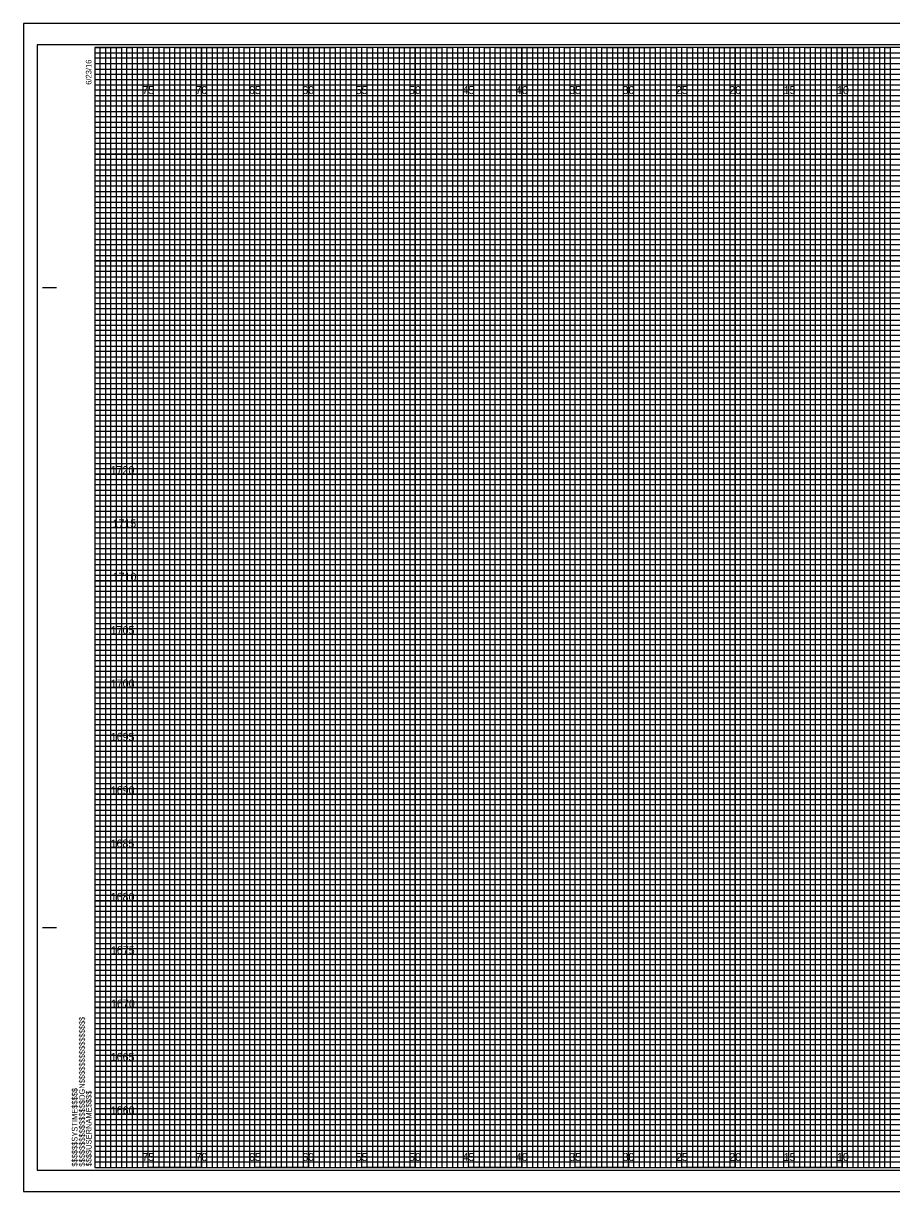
# Model space of a CAD drawing. Extents: x -407 to -239, y -3 to 766.
# Drawn here: x -407 to -325.7, y 436.6 to 546.1 of the extents above; entities that cross this region are included whole.
import ezdxf

# ---------------------------------------------------------------- set-up
doc = ezdxf.new("R2010")
doc.units = 0
for name, color, linetype in [('Raster_Level_0', 7, 'Continuous'), ('Scratch_Level_3', 7, 'Continuous'), ('Sheet Cross Section CELL', 7, 'Continuous'), ('Sheet Cross Section Grid Major CELL', 7, 'Continuous'), ('Sheet Cross Section Grid Middle CELL', 7, 'Continuous'), ('Sheet Cross Section Grid Minor 1 CELL', 7, 'Continuous'), ('Sheet Cross Section Grid Minor 2 CELL', 7, 'Continuous'), ('Sheet Cutting Line CELL', 7, 'Continuous'), ('Sheet DOT Grid CELL', 7, 'Continuous'), ('Sheet Plot Border Inside CELL', 7, 'Continuous'), ('Sheet Plot Border Outside CELL', 7, 'Continuous')]:
    doc.layers.add(name, color=color, linetype=linetype)

msp = doc.modelspace()

# ---------------------------------------------------------------- linework, layer by layer
at = {"layer": 'Sheet Cross Section CELL'}
for p, q in [((-405.22, 521.38), (-403.97, 521.38)), ((-405.17, 521.38), (-403.92, 521.38)), ((-405.22, 461.38), (-403.97, 461.38)), ((-405.17, 461.38), (-403.92, 461.38)), ((-400.32, 438.88), (-400.32, 438.88)), ((-400.32, 438.88), (-400.32, 438.88)), ((-400.32, 438.88), (-400.32, 438.88)), ((-400.32, 438.88), (-400.32, 438.88)), ((-400.32, 438.88), (-400.32, 438.88)), ((-400.32, 438.88), (-400.32, 438.88)), ((-400.32, 438.88), (-400.32, 438.88))]:
    msp.add_line(p, q, dxfattribs=at)
msp.add_lwpolyline([(-240.32, 543.88), (-400.32, 543.88), (-400.32, 438.88), (-240.32, 438.88)], close=True, dxfattribs=at)
at = {"layer": 'Sheet Cross Section Grid Major CELL'}
for p, q in [((-395.32, 543.88), (-400.32, 543.88)), ((-395.32, 438.88), (-395.32, 543.88)), ((-385.32, 543.88), (-390.32, 543.88)), ((-390.32, 543.88), (-390.32, 438.88)), ((-385.32, 438.88), (-385.32, 543.88)), ((-375.32, 543.88), (-380.32, 543.88)), ((-380.32, 543.88), (-380.32, 438.88)), ((-375.32, 438.88), (-375.32, 543.88)), ((-365.32, 543.88), (-370.32, 543.88)), ((-370.32, 543.88), (-370.32, 438.88)), ((-365.32, 438.88), (-365.32, 543.88)), ((-355.32, 543.88), (-360.32, 543.88)), ((-360.32, 543.88), (-360.32, 438.88)), ((-355.32, 438.88), (-355.32, 543.88)), ((-345.32, 543.88), (-350.32, 543.88)), ((-350.32, 543.88), (-350.32, 438.88)), ((-345.32, 438.88), (-345.32, 543.88)), ((-335.32, 543.88), (-340.32, 543.88)), ((-340.32, 543.88), (-340.32, 438.88)), ((-335.32, 438.88), (-335.32, 543.88)), ((-325.32, 543.88), (-330.32, 543.88)), ((-330.32, 543.88), (-330.32, 438.88)), ((-390.32, 438.88), (-395.32, 438.88)), ((-380.32, 438.88), (-385.32, 438.88)), ((-370.32, 438.88), (-375.32, 438.88)), ((-360.32, 438.88), (-365.32, 438.88)), ((-350.32, 438.88), (-355.32, 438.88)), ((-340.32, 438.88), (-345.32, 438.88)), ((-330.32, 438.88), (-335.32, 438.88))]:
    msp.add_line(p, q, dxfattribs=at)
for points in [[(-400.32, 538.88), (-240.32, 538.88), (-240.32, 533.88), (-400.32, 533.88)], [(-400.32, 528.88), (-240.32, 528.88), (-240.32, 523.88), (-400.32, 523.88)], [(-400.32, 518.88), (-240.32, 518.88), (-240.32, 513.88), (-400.32, 513.88)], [(-400.32, 508.88), (-240.32, 508.88), (-240.32, 503.88), (-400.32, 503.88)], [(-400.32, 498.88), (-240.32, 498.88), (-240.32, 493.88), (-400.32, 493.88)], [(-400.32, 488.88), (-240.32, 488.88), (-240.32, 483.88), (-400.32, 483.88)], [(-400.32, 478.88), (-240.32, 478.88), (-240.32, 473.88), (-400.32, 473.88)], [(-400.32, 468.88), (-240.32, 468.88), (-240.32, 463.88), (-400.32, 463.88)], [(-400.32, 458.88), (-240.32, 458.88), (-240.32, 453.88), (-400.32, 453.88)], [(-400.32, 448.88), (-240.32, 448.88), (-240.32, 443.88), (-400.32, 443.88)]]:
    msp.add_lwpolyline(points, dxfattribs=at)
at = {"layer": 'Sheet Cross Section Grid Middle CELL'}
for points in [[(-400.32, 543.88), (-397.82, 543.88), (-397.82, 438.88), (-392.82, 438.88), (-392.82, 543.88), (-387.82, 543.88), (-387.82, 438.88), (-382.82, 438.88), (-382.82, 543.88), (-377.82, 543.88), (-377.82, 438.88), (-372.82, 438.88), (-372.82, 543.88), (-367.82, 543.88), (-367.82, 438.88), (-362.82, 438.88), (-362.82, 543.88), (-357.82, 543.88), (-357.82, 438.88), (-352.82, 438.88), (-352.82, 543.88), (-347.82, 543.88), (-347.82, 438.88), (-342.82, 438.88), (-342.82, 543.88), (-337.82, 543.88), (-337.82, 438.88), (-332.82, 438.88), (-332.82, 543.88), (-327.82, 543.88), (-327.82, 438.88), (-322.82, 438.88)], [(-400.32, 541.38), (-262.82, 541.38)], [(-400.32, 531.38), (-240.32, 531.38), (-240.32, 536.38), (-400.32, 536.38)], [(-400.32, 521.38), (-240.32, 521.38), (-240.32, 526.38), (-400.32, 526.38)], [(-400.32, 511.38), (-240.32, 511.38), (-240.32, 516.38), (-400.32, 516.38)], [(-400.32, 501.38), (-240.32, 501.38), (-240.32, 506.38), (-400.32, 506.38)], [(-400.32, 491.38), (-240.32, 491.38), (-240.32, 496.38), (-400.32, 496.38)], [(-400.32, 481.38), (-240.32, 481.38), (-240.32, 486.38), (-400.32, 486.38)], [(-400.32, 471.38), (-240.32, 471.38), (-240.32, 476.38), (-400.32, 476.38)], [(-400.32, 461.38), (-240.32, 461.38), (-240.32, 466.38), (-400.32, 466.38)], [(-400.32, 451.38), (-240.32, 451.38), (-240.32, 456.38), (-400.32, 456.38)], [(-400.32, 441.38), (-240.32, 441.38), (-240.32, 446.38), (-400.32, 446.38)]]:
    msp.add_lwpolyline(points, dxfattribs=at)
at = {"layer": 'Sheet Cross Section Grid Minor 1 CELL'}
for p, q in [((-400.32, 543.38), (-270.32, 543.38)), ((-270.32, 542.87), (-400.32, 542.87)), ((-400.32, 542.87), (-400.32, 542.38)), ((-400.32, 542.38), (-270.32, 542.38)), ((-270.32, 541.82), (-400.32, 541.82)), ((-400.32, 541.82), (-400.32, 540.88)), ((-400.32, 540.88), (-240.32, 540.88))]:
    msp.add_line(p, q, dxfattribs=at)
for points in [[(-400.32, 540.38), (-265.32, 540.38), (-240.32, 540.38), (-240.32, 539.88), (-400.32, 539.88)], [(-400.32, 539.38), (-240.32, 539.38), (-240.32, 538.38), (-400.32, 538.38)], [(-400.32, 537.88), (-240.32, 537.88), (-240.32, 537.38), (-400.32, 537.37)], [(-400.32, 536.88), (-240.32, 536.88), (-240.32, 535.88), (-400.32, 535.88)], [(-400.32, 535.38), (-240.32, 535.38), (-240.32, 534.88), (-400.32, 534.88)], [(-400.32, 534.38), (-240.32, 534.38), (-240.32, 533.38), (-400.32, 533.38)], [(-400.32, 532.88), (-240.32, 532.88), (-240.32, 532.38), (-400.32, 532.38)], [(-400.32, 531.88), (-240.32, 531.88), (-240.32, 530.88), (-400.32, 530.88)], [(-400.32, 530.38), (-240.32, 530.38), (-240.32, 529.88), (-400.32, 529.88)], [(-400.32, 529.38), (-240.32, 529.38), (-240.32, 528.38), (-400.32, 528.38)], [(-400.32, 527.88), (-240.32, 527.88), (-240.32, 527.38), (-400.32, 527.38)], [(-400.32, 526.88), (-240.32, 526.88), (-240.32, 525.85), (-240.32, 525.38), (-240.32, 524.88), (-400.32, 524.88)], [(-400.32, 525.88), (-240.32, 525.88), (-240.32, 525.38), (-400.32, 525.38)], [(-400.32, 524.38), (-240.32, 524.38), (-240.32, 523.38), (-400.32, 523.39)], [(-400.32, 523.39), (-240.32, 523.38), (-240.32, 522.88), (-400.32, 522.88)], [(-400.32, 522.38), (-240.32, 522.38), (-240.32, 521.88), (-400.32, 521.88)], [(-400.32, 520.88), (-240.32, 520.88), (-240.32, 520.38), (-400.32, 520.38)], [(-400.32, 519.88), (-240.32, 519.88), (-240.32, 519.38), (-400.32, 519.38)], [(-400.35, 518.32), (-240.32, 518.32), (-240.32, 517.82), (-400.35, 517.82)], [(-400.32, 517.38), (-240.32, 517.38), (-240.32, 516.88), (-400.32, 516.88)], [(-400.32, 515.88), (-240.32, 515.88), (-240.32, 515.38), (-400.32, 515.38)], [(-400.32, 514.88), (-240.32, 514.88), (-240.32, 514.38), (-400.32, 514.38)], [(-400.32, 513.38), (-240.32, 513.38), (-240.32, 512.88), (-400.32, 512.88)], [(-400.32, 512.38), (-240.32, 512.38), (-240.32, 511.88), (-400.32, 511.88)], [(-400.32, 510.88), (-240.32, 510.88), (-240.32, 510.38), (-400.32, 510.38)], [(-400.32, 509.88), (-240.32, 509.88), (-240.32, 509.38), (-400.32, 509.38)], [(-400.32, 508.38), (-240.32, 508.38), (-240.32, 507.87), (-400.32, 507.88)], [(-400.32, 507.38), (-240.32, 507.38), (-240.32, 506.88), (-400.32, 506.88)], [(-400.32, 505.88), (-240.32, 505.88), (-240.32, 505.38), (-400.32, 505.38)], [(-400.32, 504.88), (-240.32, 504.88), (-240.32, 504.38), (-400.32, 504.38)], [(-400.32, 503.38), (-240.32, 503.38), (-240.32, 502.88), (-400.32, 502.88)], [(-400.32, 502.38), (-240.32, 502.38), (-240.32, 501.88), (-400.32, 501.88)], [(-400.32, 500.88), (-240.32, 500.88), (-240.32, 500.38), (-400.32, 500.38)], [(-400.32, 499.88), (-240.32, 499.88), (-240.32, 499.38), (-400.32, 499.38)], [(-400.32, 498.38), (-240.32, 498.38), (-240.32, 497.88), (-400.32, 497.88)], [(-400.32, 497.37), (-240.28, 497.33), (-240.32, 496.88), (-400.32, 496.88)], [(-400.32, 495.88), (-240.32, 495.88), (-240.32, 495.38), (-400.32, 495.38)], [(-400.32, 494.88), (-240.32, 494.88), (-240.32, 494.38), (-400.32, 494.38)], [(-400.32, 493.38), (-240.32, 493.38), (-240.32, 492.88), (-400.32, 492.88)], [(-400.32, 492.38), (-240.32, 492.38), (-240.32, 491.88), (-400.32, 491.88)], [(-400.32, 490.88), (-240.32, 490.88), (-240.32, 490.38), (-400.32, 490.38)], [(-400.32, 489.88), (-240.32, 489.88), (-240.32, 489.38), (-400.32, 489.38)], [(-400.32, 488.38), (-240.32, 488.38), (-240.32, 487.88), (-400.32, 487.88)], [(-400.32, 487.38), (-240.32, 487.38), (-240.32, 486.88), (-400.32, 486.88)], [(-400.32, 485.88), (-240.32, 485.88), (-240.32, 485.38), (-400.32, 485.38)], [(-400.32, 484.88), (-240.32, 484.88), (-240.32, 484.38), (-400.32, 484.38)], [(-400.32, 483.38), (-240.32, 483.38), (-240.32, 482.88), (-400.32, 482.88)], [(-400.32, 482.38), (-240.32, 482.38), (-240.32, 481.88), (-400.32, 481.88)], [(-400.32, 480.88), (-240.32, 480.88), (-240.32, 480.38), (-400.32, 480.38)], [(-400.32, 479.88), (-240.32, 479.88), (-240.32, 479.38), (-400.32, 479.38)], [(-400.32, 478.38), (-240.32, 478.38), (-240.32, 477.87), (-400.32, 477.88)], [(-400.32, 477.38), (-240.32, 477.38), (-240.32, 476.88), (-400.32, 476.88)], [(-400.32, 475.88), (-240.32, 475.88), (-240.32, 475.38), (-400.32, 475.38)], [(-400.32, 474.88), (-240.32, 474.88), (-240.32, 474.38), (-400.32, 474.38)], [(-400.32, 473.38), (-240.32, 473.38), (-240.32, 472.88), (-400.32, 472.88)], [(-400.32, 472.38), (-240.32, 472.38), (-240.32, 471.88), (-400.32, 471.88)], [(-400.32, 470.88), (-240.32, 470.88), (-240.32, 470.38), (-400.32, 470.38)], [(-400.32, 469.88), (-240.32, 469.88), (-240.32, 469.38), (-400.32, 469.38)], [(-400.32, 468.38), (-240.32, 468.38), (-240.32, 467.88), (-400.32, 467.88)], [(-400.32, 467.37), (-240.28, 467.33), (-240.32, 466.88), (-400.32, 466.88)], [(-400.32, 465.88), (-240.32, 465.88), (-240.32, 465.38), (-400.32, 465.38)], [(-400.32, 464.88), (-240.32, 464.88), (-240.32, 464.38), (-400.32, 464.38)], [(-400.32, 463.38), (-240.32, 463.38), (-240.32, 462.88), (-400.32, 462.88)], [(-400.32, 462.38), (-240.32, 462.38), (-240.32, 461.88), (-400.32, 461.88)], [(-400.32, 460.88), (-240.32, 460.88), (-240.32, 460.38), (-400.32, 460.38)], [(-400.32, 459.88), (-240.32, 459.88), (-240.32, 459.38), (-400.32, 459.38)], [(-400.32, 458.38), (-240.32, 458.38), (-240.32, 457.88), (-400.32, 457.88)], [(-400.32, 457.38), (-240.32, 457.38), (-240.32, 456.88), (-400.32, 456.88)], [(-400.32, 455.88), (-240.32, 455.88), (-240.32, 455.38), (-400.32, 455.38)], [(-400.32, 454.88), (-240.32, 454.88), (-240.32, 454.38), (-400.32, 454.38)], [(-400.32, 453.38), (-240.32, 453.38), (-240.32, 452.88), (-400.32, 452.88)], [(-400.32, 452.38), (-240.32, 452.38), (-240.32, 451.88), (-400.32, 451.88)], [(-400.32, 450.88), (-240.32, 450.88), (-240.32, 450.38), (-400.32, 450.38)], [(-400.32, 449.88), (-240.32, 449.88), (-240.32, 449.38), (-400.32, 449.38)], [(-400.32, 448.38), (-240.32, 448.38), (-240.32, 447.88), (-400.32, 447.88)], [(-400.32, 447.38), (-240.32, 447.38), (-240.32, 446.88), (-400.32, 446.88)], [(-400.32, 445.88), (-240.32, 445.88), (-240.32, 445.38), (-400.32, 445.38)], [(-400.32, 444.88), (-240.32, 444.88), (-240.32, 444.38), (-400.32, 444.38)], [(-400.32, 443.38), (-240.32, 443.38), (-240.32, 442.88), (-400.32, 442.88)], [(-400.32, 442.38), (-240.32, 442.38), (-240.32, 441.88), (-400.32, 441.88)], [(-400.32, 440.88), (-240.32, 440.88), (-240.32, 440.38), (-400.32, 440.38)], [(-400.32, 439.88), (-240.32, 439.88), (-240.32, 439.38), (-400.32, 439.38)]]:
    msp.add_lwpolyline(points, dxfattribs=at)
at = {"layer": 'Sheet Cross Section Grid Minor 2 CELL'}
for points in [[(-400.32, 438.88), (-399.82, 438.88), (-399.82, 543.88), (-399.32, 543.88), (-399.32, 438.88)], [(-399.32, 438.88), (-398.82, 438.88), (-398.82, 543.88), (-398.32, 543.88), (-398.32, 438.88)], [(-397.82, 438.88), (-397.32, 438.88), (-397.32, 543.88), (-396.82, 543.88), (-396.82, 438.88)], [(-396.82, 438.88), (-396.32, 438.88), (-396.32, 543.88), (-395.82, 543.88), (-395.82, 438.88)], [(-395.32, 438.88), (-394.82, 438.88), (-394.82, 543.88), (-394.32, 543.88), (-394.32, 438.88)], [(-394.32, 438.88), (-393.82, 438.88), (-393.82, 543.88), (-393.32, 543.88), (-393.32, 438.88)], [(-392.82, 438.88), (-392.32, 438.88), (-392.32, 543.88), (-391.82, 543.88), (-391.82, 438.88)], [(-391.82, 438.88), (-391.32, 438.88), (-391.32, 543.88), (-390.82, 543.88), (-390.82, 438.88)], [(-390.32, 438.88), (-389.82, 438.88), (-389.82, 543.88), (-389.32, 543.88), (-389.32, 438.88)], [(-389.32, 438.88), (-388.82, 438.88), (-388.82, 543.88), (-388.32, 543.88), (-388.32, 438.88)], [(-387.82, 438.88), (-387.32, 438.88), (-387.32, 543.88), (-386.82, 543.88), (-386.82, 438.88)], [(-386.82, 438.88), (-386.32, 438.88), (-386.32, 543.88), (-385.82, 543.88), (-385.82, 438.88)], [(-385.32, 438.88), (-384.82, 438.88), (-384.82, 543.88), (-384.32, 543.88), (-384.32, 438.88)], [(-384.32, 438.88), (-383.82, 438.88), (-383.82, 543.88), (-383.32, 543.88), (-383.32, 438.88)], [(-382.82, 438.88), (-382.32, 438.88), (-382.32, 543.88), (-381.82, 543.88), (-381.82, 438.88)], [(-381.82, 438.88), (-381.32, 438.88), (-381.32, 543.88), (-380.82, 543.88), (-380.82, 438.88)], [(-380.32, 438.88), (-379.82, 438.88), (-379.82, 543.88), (-379.32, 543.88), (-379.32, 438.88)], [(-379.32, 438.88), (-378.82, 438.88), (-378.82, 543.88), (-378.32, 543.88), (-378.32, 438.88)], [(-377.82, 438.88), (-377.32, 438.88), (-377.32, 543.88), (-376.82, 543.88), (-376.82, 438.88)], [(-376.82, 438.88), (-376.32, 438.88), (-376.32, 543.88), (-375.82, 543.88), (-375.82, 438.88)], [(-375.32, 438.88), (-374.82, 438.88), (-374.82, 543.88), (-374.32, 543.88), (-374.32, 438.88)], [(-374.32, 438.88), (-373.82, 438.88), (-373.82, 543.88), (-373.32, 543.88), (-373.32, 438.88)], [(-372.82, 438.88), (-372.32, 438.88), (-372.32, 543.88), (-371.82, 543.88), (-371.82, 438.88)], [(-371.82, 438.88), (-371.32, 438.88), (-371.32, 543.88), (-370.82, 543.88), (-370.82, 438.88)], [(-370.32, 438.88), (-369.82, 438.88), (-369.82, 543.88), (-369.32, 543.88), (-369.32, 438.88)], [(-369.32, 438.88), (-368.82, 438.88), (-368.82, 543.88), (-368.32, 543.88), (-368.32, 438.88)], [(-367.82, 438.88), (-367.32, 438.88), (-367.32, 543.88), (-366.82, 543.88), (-366.82, 438.88)], [(-366.82, 438.88), (-366.32, 438.88), (-366.32, 543.88), (-365.82, 543.88), (-365.82, 438.88)], [(-365.32, 438.88), (-364.82, 438.88), (-364.82, 543.88), (-364.32, 543.88), (-364.32, 438.88)], [(-364.32, 438.88), (-363.82, 438.88), (-363.82, 543.88), (-363.32, 543.88), (-363.32, 438.88)], [(-362.82, 438.88), (-362.32, 438.88), (-362.32, 543.88), (-361.82, 543.88), (-361.82, 438.88)], [(-361.82, 438.88), (-361.32, 438.88), (-361.32, 543.88), (-360.82, 543.88), (-360.82, 438.88)], [(-360.32, 438.88), (-359.82, 438.88), (-359.82, 543.88), (-359.32, 543.88), (-359.32, 438.88)], [(-359.32, 438.88), (-358.82, 438.88), (-358.82, 543.88), (-358.32, 543.88), (-358.32, 438.88)], [(-357.82, 438.88), (-357.32, 438.88), (-357.32, 543.88), (-356.82, 543.88), (-356.82, 438.88)], [(-356.82, 438.88), (-356.32, 438.88), (-356.32, 543.88), (-355.82, 543.88), (-355.82, 438.88)], [(-355.32, 438.88), (-354.82, 438.88), (-354.82, 543.88), (-354.32, 543.88), (-354.32, 438.88)], [(-354.32, 438.88), (-353.82, 438.88), (-353.82, 543.88), (-353.32, 543.88), (-353.32, 438.88)], [(-352.82, 438.88), (-352.32, 438.88), (-352.32, 543.88), (-351.82, 543.88), (-351.82, 438.88)], [(-351.82, 438.88), (-351.32, 438.88), (-351.32, 543.88), (-350.82, 543.88), (-350.82, 438.88)], [(-350.32, 438.88), (-349.82, 438.88), (-349.82, 543.88), (-349.32, 543.88), (-349.32, 438.88)], [(-349.32, 438.88), (-348.82, 438.88), (-348.82, 543.88), (-348.32, 543.88), (-348.32, 438.88)], [(-347.82, 438.88), (-347.32, 438.88), (-347.32, 543.88), (-346.82, 543.88), (-346.82, 438.88)], [(-346.82, 438.88), (-346.32, 438.88), (-346.32, 543.88), (-345.82, 543.88), (-345.82, 438.88)], [(-345.32, 438.88), (-344.82, 438.88), (-344.82, 543.88), (-344.32, 543.88), (-344.32, 438.88)], [(-344.32, 438.88), (-343.82, 438.88), (-343.82, 543.88), (-343.32, 543.88), (-343.32, 438.88)], [(-342.82, 438.88), (-342.32, 438.88), (-342.32, 543.88), (-341.82, 543.88), (-341.82, 438.88)], [(-341.82, 438.88), (-341.32, 438.88), (-341.32, 543.88), (-340.82, 543.88), (-340.82, 438.88)], [(-340.32, 438.88), (-339.82, 438.88), (-339.82, 543.88), (-339.32, 543.88), (-339.32, 438.88)], [(-339.32, 438.88), (-338.82, 438.88), (-338.82, 543.88), (-338.32, 543.88), (-338.32, 438.88)], [(-337.82, 438.88), (-337.32, 438.88), (-337.32, 543.88), (-336.82, 543.88), (-336.82, 438.88)], [(-336.82, 438.88), (-336.32, 438.88), (-336.32, 543.88), (-335.82, 543.88), (-335.82, 438.88)], [(-335.32, 438.88), (-334.82, 438.88), (-334.82, 543.88), (-334.32, 543.88), (-334.32, 438.88)], [(-334.32, 438.88), (-333.82, 438.88), (-333.82, 543.88), (-333.32, 543.88), (-333.32, 438.88)], [(-332.82, 438.88), (-332.32, 438.88), (-332.32, 543.88), (-331.82, 543.88), (-331.82, 438.88)], [(-331.82, 438.88), (-331.32, 438.88), (-331.32, 543.88), (-330.82, 543.88), (-330.82, 438.88)], [(-330.32, 438.88), (-329.82, 438.88), (-329.82, 543.88), (-329.32, 543.88), (-329.32, 438.88)], [(-329.32, 438.88), (-328.82, 438.88), (-328.82, 543.88), (-328.32, 543.88), (-328.32, 438.88)], [(-327.82, 438.88), (-327.32, 438.88), (-327.32, 543.88), (-326.82, 543.88), (-326.82, 438.88)], [(-326.82, 438.88), (-326.32, 438.88), (-326.32, 543.88), (-325.82, 543.88), (-325.82, 438.88)]]:
    msp.add_lwpolyline(points, dxfattribs=at)
at = {"layer": 'Sheet Cutting Line CELL'}
for p, q in [((-238.67, 546.13), (-407.02, 546.13)), ((-407.02, 546.13), (-407.02, 436.63)), ((-407.02, 436.63), (-238.67, 436.63))]:
    msp.add_line(p, q, dxfattribs=at)
at = {"layer": 'Sheet DOT Grid CELL'}
for p, q in [((-395.32, 438.88), (-395.32, 543.88)), ((-390.32, 438.88), (-390.32, 543.88)), ((-385.32, 438.88), (-385.32, 543.88)), ((-380.32, 438.88), (-380.32, 543.88)), ((-375.32, 438.88), (-375.32, 543.88)), ((-370.32, 438.88), (-370.32, 543.88)), ((-365.32, 438.88), (-365.32, 543.88)), ((-360.32, 438.88), (-360.32, 543.88)), ((-355.32, 438.88), (-355.32, 543.88)), ((-350.32, 438.88), (-350.32, 543.88)), ((-345.32, 438.88), (-345.32, 543.88)), ((-340.32, 438.88), (-340.32, 543.88)), ((-335.32, 438.88), (-335.32, 543.88)), ((-330.32, 438.88), (-330.32, 543.88)), ((-400.32, 538.88), (-240.32, 538.88)), ((-400.32, 533.88), (-240.32, 533.88)), ((-400.32, 528.88), (-240.32, 528.88)), ((-400.32, 523.88), (-240.32, 523.88)), ((-400.32, 518.88), (-240.32, 518.88)), ((-400.32, 513.88), (-240.32, 513.88)), ((-400.32, 508.88), (-240.32, 508.88)), ((-400.32, 503.88), (-240.32, 503.88)), ((-400.32, 498.88), (-240.32, 498.88)), ((-400.32, 493.88), (-240.32, 493.88)), ((-400.32, 488.88), (-240.32, 488.88)), ((-400.32, 483.88), (-240.32, 483.88)), ((-400.32, 478.88), (-240.32, 478.88)), ((-400.32, 473.88), (-240.32, 473.88)), ((-400.32, 468.88), (-240.32, 468.88)), ((-400.32, 463.88), (-240.32, 463.88)), ((-400.32, 458.88), (-240.32, 458.88)), ((-400.32, 453.88), (-240.32, 453.88)), ((-400.32, 448.88), (-240.32, 448.88)), ((-400.32, 443.88), (-240.32, 443.88))]:
    msp.add_line(p, q, dxfattribs=at)
at = {"layer": 'Sheet Plot Border Inside CELL'}
msp.add_lwpolyline([(-405.72, 438.63), (-239.12, 438.63), (-239.12, 544.13), (-405.72, 544.13)], close=True, dxfattribs=at)
at = {"layer": 'Sheet Plot Border Outside CELL'}
msp.add_lwpolyline([(-407.02, 436.63), (-238.67, 436.63), (-238.67, 546.13), (-407.02, 546.13)], close=True, dxfattribs=at)

# ---------------------------------------------------------------- texts
at = {"layer": 'Raster_Level_0'}
for s, p in [('75', (-395.88, 539.5)), ('70', (-390.89, 539.5)), ('65', (-385.88, 539.5)), ('60', (-380.89, 539.5)), ('55', (-375.88, 539.5)), ('50', (-370.89, 539.5)), ('45', (-365.88, 539.5)), ('40', (-360.89, 539.5)), ('35', (-355.88, 539.5)), ('30', (-350.89, 539.5)), ('25', (-345.88, 539.5)), ('20', (-340.89, 539.5)), ('15', (-335.79, 539.5)), ('10', (-330.8, 539.5)), ('75', (-395.88, 439.5)), ('70', (-390.89, 439.5)), ('65', (-385.88, 439.5)), ('60', (-380.89, 439.5)), ('55', (-375.88, 439.5)), ('50', (-370.89, 439.5)), ('45', (-365.88, 439.5)), ('40', (-360.89, 439.5)), ('35', (-355.88, 439.5)), ('30', (-350.89, 439.5)), ('25', (-345.88, 439.5)), ('20', (-340.89, 439.5)), ('15', (-335.79, 439.5)), ('10', (-330.8, 439.5))]:
    msp.add_text(s, height=0.75, dxfattribs=at).set_placement(p)
at = {"layer": 'Scratch_Level_3'}
for s, p in [('1720', (-398.85, 503.88)), ('1715', (-398.67, 498.88)), ('1710', (-398.66, 493.88)), ('1705', (-398.84, 488.88)), ('1700', (-398.83, 483.88)), ('1695', (-398.84, 478.88)), ('1690', (-398.83, 473.88)), ('1685', (-398.85, 468.88)), ('1680', (-398.84, 463.88)), ('1675', (-398.82, 458.88)), ('1670', (-398.81, 453.88)), ('1665', (-398.84, 448.88)), ('1660', (-398.83, 443.88))]:
    msp.add_text(s, height=0.75, dxfattribs=at).set_placement(p)
at = {"layer": 'Sheet Cross Section CELL'}
for s, p in [('6/23/16', (-400.64, 540.38)), ('$$$$$$$$$$$$$$$$DGN$$$$$$$$$$$$$$$$', (-401.26, 438.97)), ('$$$$$$SYSTIME$$$$$', (-401.95, 438.97)), ('$$$$USERNAME$$$$', (-400.63, 438.99))]:
    msp.add_text(s, height=0.525, rotation=90, dxfattribs=at).set_placement(p)

doc.saveas('drawing.dxf')
